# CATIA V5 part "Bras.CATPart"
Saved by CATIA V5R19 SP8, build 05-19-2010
Part number: Bras
Bounding box of the stored display mesh (mm): x -300 to 300, y -615.988 to 313.272, z 1181.042 to 1414.984
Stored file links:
  G:\EU_thinkMotion\CFAO_2010\MMS_groupe2\MMS_groupe2\OK\nrosalie\nrosalie_cfao_support_d_arme_legere_final\Bras.CATPart
  G:\EU_thinkMotion\CFAO_2010\MMS_groupe2\MMS_groupe2\OK\nrosalie\nrosalie_cfao_support_d_arme_legere_final\nrosalie_Support_d_arme_legere.CATProduct
  G:\EU_thinkMotion\CFAO_2010\MMS_groupe2\MMS_groupe2\OK\nrosalie\nrosalie_cfao_support_d_arme_legere_final\Squelette_Colone.CATPart
  G:\EU_thinkMotion\CFAO_2010\MMS_groupe2\MMS_groupe2\OK\nrosalie\nrosalie_cfao_support_d_arme_legere_final\Piece_de_support.CATPart
  G:\EU_thinkMotion\CFAO_2010\MMS_groupe2\MMS_groupe2\OK\nrosalie\nrosalie_cfao_support_d_arme_legere_final\Squelette_Systeme_de_visee.CATPart
  G:\EU_thinkMotion\CFAO_2010\MMS_groupe2\MMS_groupe2\OK\nrosalie\nrosalie_cfao_support_d_arme_legere_final\Squelette_piece_support.CATPart
  G:\EU_thinkMotion\CFAO_2010\MMS_groupe2\MMS_groupe2\OK\nrosalie\nrosalie_cfao_support_d_arme_legere_final\Squelette_bras.CATPart
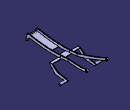
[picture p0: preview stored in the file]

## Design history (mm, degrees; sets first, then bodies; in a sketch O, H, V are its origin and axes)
Set1
  Sketch1 on Plane1, origin (0, -1.682, 1094.7588), H (1, 0, 0), V (0, 0.9999, 0.0173)
    line L1 (-150, 320.1819) -> (-130, 320.1819)
    line L2 (-130, 320.1819) -> (-130, 290.1819)
    line L3 (-130, 290.1819) -> (-135, 290.1819)
    line L4 (-150, 290.1819) -> (-150, 320.1819)
    line L5 (-145.2686, 290.1819) -> (-69.4353, -34.8181)
    point P6 (-69.4353, -34.8181)
    line L6 (-135, 290.1819) -> (-59.1667, -34.8181)
    point P8 (-59.1667, -34.8181)
    line L7 (-59.1667, -34.8181) -> (-59.1667, -624.8181)
    point P9 (-59.1667, -34.8181)
    line L8 (-69.4353, -34.8181) -> (-69.4353, -634.8181)
    point P11 (-69.4353, -34.8181)
    line L9 (-145.2686, 290.1819) -> (-150, 290.1819)
    construction line L10 (-130, 247.183) -> (-130, 159.7527)
    line L11 (-69.4353, -634.8181) -> (-59.1667, -634.8181)
    axis line L12 (403.9745, -34.8181) -> (-248.0728, -34.8181)
    reference intersected line E1 through (-150, 0) direction (0, 1) from Plane4
    reference projected point E2 (0, 5.1819) from Point1
    reference intersected line E3 through (-150, 0) direction (0, 1) from Plane4
    reference projected line E4 (-500, 305.1819) -> (500, 305.1819) from Line3
    reference projected line E5 (-500, 305.1819) -> (500, 305.1819) from Line3
    reference projected line E6 (-87.6829, -4.7485) -> (-158.8533, 300.2676) from Line4
    line L13 (130, 320.1819) -> (150, 320.1819)
    line L14 (150, 320.1819) -> (150, 290.1819)
    line L15 (150, 290.1819) -> (145.2686, 290.1819)
    line L16 (130, 320.1819) -> (130, 290.1819)
    point P21 (130, 290.1819)
    line L17 (130, 290.1819) -> (135, 290.1819)
    line L18 (135, 290.1819) -> (59.1667, -34.8181)
    line L19 (59.1667, -624.8181) -> (59.1667, -34.8181)
    line L20 (59.1667, -634.8181) -> (69.4353, -634.8181)
    line L21 (69.4353, -634.8181) -> (69.4353, -34.8181)
    line L22 (69.4353, -34.8181) -> (145.2686, 290.1819)
    reference projected line E7 (0, 300) -> (0, 0) from Line8
    reference projected line E8 (0, 300) -> (0, 0) from Line8
    reference projected line E9 (0, 300) -> (0, 0) from Line8
    reference projected line E10 (0, 300) -> (0, 0) from Line8
    reference projected line E11 (0, 300) -> (0, 0) from Line8
    reference projected line E12 (0, 300) -> (0, 0) from Line8
    reference projected line E13 (0, -600) -> (0, 200) from Line1
    reference projected line E14 (0, 300) -> (0, 0) from Line8
    reference projected line E15 (0, 300) -> (0, 0) from Line8
    line L23 (-59.1667, -624.8181) -> (59.1667, -624.8181)
    line L24 (-59.1667, -634.8181) -> (59.1667, -634.8181)
    distance E2 L12 = 40
    distance L2 E3 = 20
    distance L6 L5 = 10
    distance L1 E5 = 15
    distance L11 L12 = 600
    length L3 = 5
    distance L23 L24 = 10
    coincidence: L4 E1, P6 P11, P9 P8, P8 L12, L12 P6, L3 L9, P21 L15
    symmetry: L1 L9 E4, L13 L1 E7, L16 L2 E8, L14 L4 E9, L17 L3 E10, L18 L6 E11, L22 L5 E12, L19 L7 E13, L8 L21 E14, L20 L11 E15
    parallelism: L5 E6, L8 L7
    horizontal: L12 H, L13 H, L15 H, L17 H, L20 H, L23 H, L24 H
    vertical: L7 V, L14 V, L16 V, L19 V, L21 V
  Sketch2 on Plane4, origin (-150, 0, 0), H (0, 1, 0), V (0, 0, 1)
    construction circle A1 centre (-150.2783, 1312.2247) radius 15
    point P1 (-150.2783, 1312.2247)
    spline S1 through (293.4591, 1414.1917) (-151.098, 1327.2023) (-597.7953, 1364.1019)
    spline S2 through (303.0854, 1385.7781) (-149.4586, 1297.2471) (-604.1803, 1334.7893)
    arc A2 centre (-600.9884, 1349.4457) radius 15 from (-597.7953, 1364.1019) to (-604.1803, 1334.7893) ccw
    point P2 (-600.9884, 1349.4457)
    arc A3 centre (298.2728, 1399.9851) radius 15 from (303.0854, 1385.7781) to (293.4591, 1414.1917) ccw
    point P4 (-604.1803, 1334.7893)
    point P5 (-597.7953, 1364.1019)
    point P6 (293.4591, 1414.1917)
    point P7 (303.0854, 1385.7781)
    reference projected point E1 (-150.2783, 1312.2247) from Point3
    reference projected point E2 (-600.9884, 1349.4457) from Point4
    reference projected point E3 (298.2728, 1399.9851) from Point2
    reference projected point E4 (298.2728, 1399.9851) from Point2
    point P8 (-151.098, 1327.2023)
    point P9 (-149.4586, 1297.2471)
    point P10 (303.0854, 1385.7781)
    point P11 (293.4591, 1414.1917)
    point P12 (-597.7953, 1364.1019)
    point P13 (-604.1803, 1334.7893)
    radius A2 = 15
    radius A1 = 15
    distance E3 A3 = 15
    tangency: S1 A1, A1 S2, A2 S2, S1 A2, S1 A3, S2 A3
    coincidence: P8 A1, P9 A1, P1 E1, P2 E2, P5 P12, P13 P4, P6 P11, P7 P10
    concentricity: A3 E4
Set2
  Plane1 "Plan_limite_inferieur_liaison_pivot_colone_systeme": linked copy from another document
  Plane2 "Plan_limite_inferieur_de_l_arme": linked copy from another document
  Line1: linked copy from another document
  Plane3: linked copy from another document
  Line2 "Axe_vertical_colonne": linked copy from another document
  Plane4 "Interphase_pivot_permettant _la_rotation_en_site": linked copy from another document
  Point1 "Centre_liaison_pivot__systeme_de_visee": linked copy from another document
  Line3 "Axe_de_rotation_en_site": linked copy from another document
  Line4: linked copy from another document
  Point2 "Centre_de_la_pivot": linked copy from another document
  Point3 to Point5: linked copy from another document
  Plane5: linked copy from another document
  Line5: linked copy from another document
  DatumPoint1: linked copy from another document
  Line6: linked copy from another document
  DatumPoint2: linked copy from another document
  Plane6: linked copy from another document
  Line7: linked copy from another document
  Line8: linked copy from another document
  Plane7: linked copy from another document
  Plane8: linked copy from another document
  DatumPoint3: linked copy from another document
  DatumPoint4: linked copy from another document
Body1 (main body)
  SolidCombine1: FirstComponentProfile Sketch2, FirstComponentDirection Sketch2, SecondComponentProfile Sketch1, SecondComponentDirection Sketch1
  Sketch3 on face of SolidCombine1 from Sketch1.L8, origin (-69.4353, 0, 0), H (0, -1, 0), V (0, 0, 1)
    circle A1 centre (600.9884, 1349.4457) radius 5
    reference projected point E1 (600.9884, 1349.4457) from Point4
    radius A1 = 5
    concentricity: A1 E1
  Pocket1: profile Sketch3, direction (1, 0, 0), up to face of SolidCombine1 from Sketch1.L7
  Sketch4 on face of SolidCombine1 from Sketch1.L4, origin (-150, 0, 0), H (0, -1, 0), V (0, 0, 1)
    circle A1 centre (-298.2728, 1399.9851) radius 7.5
    reference projected point E1 (-298.2728, 1399.9851) from Point2
    radius A1 = 7.5
    concentricity: A1 E1
  Pocket2: profile Sketch4, direction (1, 0, 0), up to face of SolidCombine1 from Sketch1.L2
  Sketch5 on face of SolidCombine1 from Sketch1.L8, origin (-69.4353, 0, 0), H (0, -1, 0), V (0, 0, 1)
    circle A1 centre (150.2783, 1312.2247) radius 5
    reference projected point E1 (150.2783, 1312.2247) from Point3
    radius A1 = 5
    concentricity: A1 E1
  Pocket3: profile Sketch5, direction (1, 0, 0), up to face of SolidCombine1 from Sketch1.L7
  Sketch6 on Plane2, origin (0, -1.6824, 1344.7961), H (1, 0, 0), V (0, 0.9999, 0.0173)
    point P1 (-69.4353, -119.1363)
    line L1 (-69.4353, -119.1363) -> (69.4353, -119.1363)
    line L2 (59.1667, -199.1363) -> (-59.1667, -199.1363)
    point P3 (-69.4353, -119.1363)
    line L3 (-59.1667, -299.1363) -> (59.1667, -299.1363)
    line L4 (69.4353, -599.1363) -> (-69.4353, -599.1363)
    line L5 (-69.4353, -599.1363) -> (-69.4353, -119.1363)
    reference projected line E1 (-69.4353, -593.3086) -> (-69.4353, -54.6163) from edge [face of SolidCombine1 from Sketch2.S1 | face of SolidCombine1 from Sketch1.L8]
    reference projected point E2 (0, -149.1363) from Point3
    reference projected point E3 (0, -149.1363) from Point3
    line L6 (-59.1667, -199.1363) -> (-59.1667, -299.1363)
    reference projected line E4 (-59.1667, -593.3086) -> (-59.1667, -54.6163) from edge [face of SolidCombine1 from Sketch1.L7 | face of SolidCombine1 from Sketch2.S1]
    reference projected line E5 (-85, -599.1363) -> (0, -599.1363) from Line7
    line L7 (59.1667, -199.1363) -> (59.1667, -231.1922)
    line L8 (69.4353, -119.1363) -> (69.4353, -231.1922)
    reference projected line E6 (59.1667, -596.5542) -> (59.1667, -40) from edge [face of SolidCombine1 from Sketch2.S1 | face of SolidCombine1 from Sketch1.L19]
    reference projected line E7 (69.4353, -596.5542) -> (69.4353, -40) from edge [face of SolidCombine1 from Sketch1.L21 | face of SolidCombine1 from Sketch2.S1]
    line L9 (59.1667, -231.1922) -> (69.4353, -231.1922)
    line L10 (59.1667, -237.5915) -> (69.4353, -237.5915)
    point P12 (59.1667, -237.5915)
    point P13 (69.4353, -237.5915)
    line L11 (69.4353, -237.5915) -> (69.4353, -599.1363)
    line L12 (59.1667, -237.5915) -> (59.1667, -299.1363)
    distance E2 L1 = 30
    distance L2 E3 = 50
    distance L3 L2 = 100
    horizontal: L1 H, L2 H, L3 H, L4 H, L9 H, L10 H
    vertical: L5 V, L6 V, L7 V, L8 V, L11 V, L12 V
    coincidence: L5 E1, P3 P1, L6 E4, L4 E5, L7 E6, L8 E7, P12 L7, P13 L8, L8 L11, L7 L12
  Sketch7 on yz-plane, origin (0, 0, 0), H (0, 1, 0), V (0, 0, 1)
    projected curve E1 from edge [face of SolidCombine1 from Sketch1.L8 | face of SolidCombine1 from Sketch2.S2]
    projected curve E2 from edge [face of SolidCombine1 from Sketch1.L8 | face of SolidCombine1 from Sketch2.S2]
    construction circle A1 centre (-600.9884, 1349.4457) radius 20
    construction circle A2 centre (-150.2783, 1312.2247) radius 20
    construction circle A3 centre (298.2728, 1399.9851) radius 20
    reference projected point E3 (298.2728, 1399.9851) from Point2
    reference projected point E4 (-150.2783, 1312.2247) from Point3
    reference projected point E5 (-600.9884, 1349.4457) from Point4
    spline S1 through (304.6893, 1381.0423) (-149.1854, 1292.2546) (-605.244, 1329.9037)
    line L1 (-40.17, 1306.9035) -> (-40.17, 1301.8667)
    line L2 (-600.7223, 1334.0397) -> (-600.6336, 1328.9059)
    point P7 (-600.7223, 1334.0397)
    reference projected line E6 (-602.1205, 1414.9817) -> (-605.5749, 1614.9519) from Line5
    point P9 (-149.1854, 1292.2546)
    point P10 (304.6893, 1381.0423)
    point P11 (-605.244, 1329.9037)
    radius A3 = 20 {= Sketch7.radius(A1)}
    radius A2 = 20 {= Sketch7.radius(A1)}
    radius A1 = 20
    concentricity: A3 E3, A2 E4, A1 E5
    coincidence: P9 A2, P10 A3, P11 A1, P7 E1, L2 E6
    tangency: S1 A2, S1 A3, S1 A1
    vertical: L1 V, L2 V
  SolidCombine2: FirstComponentProfile Sketch6, FirstComponentDirection Sketch6, SecondComponentProfile Sketch7, SecondComponentDirection Sketch7
  Sketch8 on yz-plane, origin (0, 0, 0), H (0, 1, 0), V (0, 0, 1)
    line L1 (-170.2783, 1296.2405) -> (-170.2783, 1291.2362)
    point P1 (-170.2783, 1296.2405)
    point P2 (-170.2783, 1291.2362)
    line L2 (-130.2783, 1293.3987) -> (-130.2783, 1298.4097)
    point P3 (-130.2783, 1293.3987)
    point P4 (-130.2783, 1298.4097)
    reference projected point E1 (-150.2783, 1312.2247) from Point3
    point P5 (-130.2783, 1293.3987)
    point P6 (-130.2783, 1298.4097)
    point P7 (-170.2783, 1296.2405)
    projected arc E2 centre (-239.0118, 2933.5473) radius 1638.7489 from (-199.9928, 1295.263) to (-120.0475, 1299.1222) ccw from edge [face of SolidCombine1 | face of SolidCombine2 from Sketch7.E2]
    projected arc E3 centre (-239.0118, 2933.5473) radius 1638.7489 from (-170.2783, 1296.2405) to (-130.2783, 1298.4097) ccw from edge [face of SolidCombine1 | face of SolidCombine2 from Sketch7.E2]
    projected curve E4 from edge [face of SolidCombine2 from Sketch7.S1 | face of SolidCombine1]
    projected curve E5 from edge [face of SolidCombine2 from Sketch7.S1 | face of SolidCombine1]
    point P12 (-130.2783, 1293.3987)
    point P13 (-130.2783, 1298.4097)
    point P14 (-170.2783, 1296.2405)
    point P15 (-170.2783, 1291.2362)
    distance L1 L2 = 40
    vertical: L1 V, L2 V
    equidistance: L2 L1 E1
    coincidence: L2 P5, L2 P6, L1 P7, P1 P7, P3 P5, P4 P6, L2 P12, L2 P13, L1 P14, L1 P15, P4 P13, P3 P12, P2 P15, P14 P1
  Pad1: profile Sketch8, direction (-1, 0, 0), up to Plane5, opposite side up to Plane7
  Sketch9 on Plane8, origin (150, 0, 0), H (0, 1, 0), V (0, 0, 1)
    circle A1 centre (298.2728, 1399.9851) radius 7.5
    reference projected circle E1 centre (298.2728, 1399.9851) radius 7.5 from edge [face of SolidCombine1 from Sketch1.L2 | face of Pocket2 from Sketch4.A1]
    coincidence: A1 E1
  Pocket4: profile Sketch9, direction (-1, 0, 0), up to face of SolidCombine1 from Sketch1.L16
  Sketch10 on face of SolidCombine1, origin (69.4353, 0, 0), H (0, 1, 0), V (0, 0, 1)
    circle A1 centre (-150.2783, 1312.2247) radius 5
    circle A2 centre (-600.9884, 1349.4457) radius 5
    reference projected circle E1 centre (-600.9884, 1349.4457) radius 5 from edge [face of Pocket1 from Sketch3.A1 | face of SolidCombine1 from Sketch1.L7]
    reference projected circle E2 centre (-150.2783, 1312.2247) radius 5 from edge [face of Pocket3 from Sketch5.A1 | face of SolidCombine1 from Sketch1.L7]
    coincidence: A2 E1, A1 E2
  Pocket5: profile Sketch10, direction (-1, 0, 0), up to face of SolidCombine1
  Sketch11 on end face of Pad1, origin (-200, 0, 0), H (0, -1, 0), V (0, 0, 1)
    arc A1 centre (-71.7615, 1196.0424) radius 15 from (-74.0179, 1210.8717) to (-70.562, 1181.0904) ccw
    reference projected point E1 (-71.7615, 1196.0424) from vertex of DatumPoint3
    line L1 (-74.0179, 1210.8717) -> (49.7803, 1229.7089)
    point P3 (49.7803, 1229.7089)
    line L2 (49.7803, 1229.7089) -> (130.2783, 1293.3987)
    point P4 (49.7803, 1229.7089)
    point P5 (130.2783, 1293.3987)
    line L3 (130.2783, 1293.3987) -> (170.2783, 1291.2362)
    point P6 (170.2783, 1291.2362)
    line L4 (170.2783, 1291.2362) -> (87.471, 1193.7685)
    point P7 (87.471, 1193.7685)
    line L5 (87.471, 1193.7685) -> (-70.562, 1181.0904)
    point P9 (87.471, 1193.7685)
    reference projected point E2 (130.2783, 1293.3987) from vertex [face of Pad1 from Sketch8.L2 | face of Pad1 from Sketch8.E5 | end face of Pad1]
    reference projected point E3 (170.2783, 1291.2362) from vertex [end face of Pad1 | face of Pad1 from Sketch8.E5 | face of Pad1 from Sketch8.L1]
    radius A1 = 15
    concentricity: A1 E1
    tangency: L5 A1, L1 A1
    coincidence: P3 P4, P9 P7, P5 E2, P6 E3
  Pad2: profile Sketch11, direction (1, 0, 0), length 10
  Sketch12 on Plane5, origin (-200, 0, 0), H (0, 1, 0), V (0, 0, 1)
    circle A1 centre (71.7615, 1196.0424) radius 15
    reference projected point E1 (71.7615, 1196.0424) from Point5
    concentricity: A1 E1
  Pad3: profile Sketch12, direction (-1, 0, 0), length 100
  Fillet1: radius 5, on end face of Pad3
  Sketch13 on face of SolidCombine1, origin (-69.4353, 0, 0), H (0, -1, 0), V (0, 0, 1)
    point P1 (585.9884, 1349.4457)
    line L1 (615.9884, 1349.4457) -> (615.9884, 1299.4532)
    line L2 (585.9884, 1306.6515) -> (585.9884, 1349.4457)
    point P2 (615.9884, 1349.4457)
    point P3 (615.9884, 1299.4532)
    point P4 (585.9884, 1306.6515)
    projected circle E1 centre (600.9884, 1349.4457) radius 5 from edge [face of SolidCombine1 | face of Pocket1 from Sketch3.A1]
    projected arc E2 centre (600.9884, 1349.4457) radius 5 from (595.9884, 1349.4457) to (605.9884, 1349.4457) ccw from edge [face of SolidCombine1 | face of Pocket1 from Sketch3.A1]
    line L3 (595.9884, 1349.4457) -> (585.9884, 1349.4457)
    point P5 (595.9884, 1349.4457)
    point P6 (585.9884, 1349.4457)
    line L4 (605.9884, 1349.4457) -> (615.9884, 1349.4457)
    point P7 (605.9884, 1349.4457)
    point P8 (615.9884, 1349.4457)
    reference projected point E3 (600.9884, 1349.4457) from Point4
    reference projected arc E4 centre (600.9884, 1349.4457) radius 15 from (603.6998, 1334.6928) to (598.2768, 1364.1986) ccw from edge [face of SolidCombine1 from Sketch2.A2 | face of SolidCombine1 from Sketch1.L8]
    arc A1 centre (600.1248, 1299.4532) radius 15.8636 from (585.9884, 1306.6515) to (615.9884, 1299.4532) ccw
    reference projected point E5 (600.1248, 1299.4532) from DatumPoint1
    point P10 (585.9884, 1306.6515)
    point P11 (615.9884, 1299.4532)
    reference projected point E6 (600.9884, 1349.4457) from Point4
    vertical: L1 V, L2 V
    coincidence: P5 E1, P6 L2, P7 L3, P7 E1, P8 L1, P8 P2, P6 P1, P3 A1, P4 A1, L1 P11, L2 P10, L4 E6, P3 P11, P4 P10
    horizontal: L3 H, L4 H
    equidistance: L1 L2 E3
    tangency: L1 E4, A1 L1
    concentricity: A1 E5
  Pad4: profile Sketch13, direction (-1, 0, 0), up to face of SolidCombine1
  Sketch14 on face of SolidCombine1, origin (-59.1667, 0, 0), H (0, 1, 0), V (0, 0, 1)
    projected line E1 (-600.7223, 1334.0397) -> (-600.6336, 1328.9059) from edge [face of SolidCombine1 | face of SolidCombine2 from Sketch7.L2]
    projected arc E2 centre (-216.8117, 3113.4761) radius 1825.3794 from (-600.6336, 1328.9059) to (-585.9884, 1325.8188) ccw from edge [face of SolidCombine2 from Sketch7.S1 | face of SolidCombine1]
    projected line E3 (-585.9884, 1325.8188) -> (-585.9884, 1306.6515) from edge [face of SolidCombine1 | face of Pad4 from Sketch13.L2]
    projected arc E4 centre (-600.1248, 1299.4532) radius 15.8636 from (-615.9884, 1299.4532) to (-585.9884, 1306.6515) ccw from edge [face of SolidCombine1 | face of Pad4 from Sketch13.A1]
    point P7 (-615.9884, 1299.4532)
    projected line E5 (-615.9884, 1299.4532) -> (-615.9884, 1349.4457) from edge [face of SolidCombine1 | face of Pad4 from Sketch13.L1]
    projected line E6 (-615.9884, 1299.4532) -> (-615.9884, 1334.0397) from edge [face of SolidCombine1 | face of Pad4 from Sketch13.L1]
    point P9 (-615.9884, 1299.4532)
    line L1 (-600.7223, 1334.0397) -> (-615.9884, 1334.0397)
    point P11 (-615.9884, 1334.0397)
    coincidence: P11 E5, P7 P9
    horizontal: L1 H
  Pad5: profile Sketch14, direction (1, 0, 0), up to face of SolidCombine1
  Sketch15 on Plane6, origin (0, -1.6823, 1309.7909), H (1, 0, 0), V (0, 0.9999, 0.0173)
    line L1 (95, -603.5318) -> (-95, -603.5318)
    line L2 (-95, -598.5318) -> (95, -598.5318)
    reference projected line E1 (-75, -598.5318) -> (0, -598.5318) from Line7
    line L3 (95, -598.5318) -> (95, -603.5318)
    reference projected point E2 (85, -598.5318) from vertex of DatumPoint4
    line L4 (-95, -598.5318) -> (-95, -603.5318)
    reference projected point E3 (-85, -598.5318) from vertex of DatumPoint2
    distance L1 L2 = 5
    distance L3 E2 = 10
    distance L4 E3 = 10
    coincidence: L2 E1
    vertical: L3 V, L4 V
  Shaft1: profile Sketch15, axis Sketch15.L2, angle 360
  Sketch16 on start face of Pad1, origin (200, 0, 0), H (0, 1, 0), V (0, 0, 1)
  Pad6: profile Sketch16, direction (-1, 0, 0), length 10
  Sketch17 on Plane7, origin (200, 0, 0), H (0, 1, 0), V (0, 0, 1)
    circle A1 centre (71.7614, 1196.0424) radius 15
    reference projected arc E1 centre (71.7614, 1196.0424) radius 15 from (70.562, 1181.0904) to (74.0179, 1210.8717) ccw from edge [face of Pad6 | start face of Pad6]
    coincidence: A1 E1
  Pad7: profile Sketch17, direction (1, 0, 0), length 100
  Fillet2: radius 5, on edge [face of Pad7 from Sketch17.A1 | end face of Pad7]
  Sketch18 on face of SolidCombine1, origin (69.4353, 0, 0), H (0, 1, 0), V (0, 0, 1)
  Pad8: profile Sketch18, direction (1, 0, 0), up to face of SolidCombine1
  Line9: type PtPt, FirstPoint DatumPoint1, SecondPoint DatumPoint2, Start 50
  Plane9: type Normal, Curve Line9, RefPoint DatumPoint1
